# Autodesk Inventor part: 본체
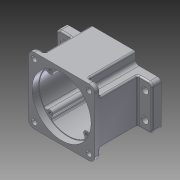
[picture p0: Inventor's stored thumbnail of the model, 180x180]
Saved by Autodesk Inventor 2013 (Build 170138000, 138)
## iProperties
Created: 2015-07
Part Number: 본체
Material: 알루미늄 6061
Document SubType Name: Modeling
Designer: user
Density: 2.71 g/cm^3
Mass: 705.328 g
Surface Area: 672.952 cm^2
Volume: 260.268 cm^3
Author: user
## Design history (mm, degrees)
sketch "스케치1"
  geometry: L1 (-45, 45)-(45, 45); L2 (45, 45)-(45, -45); L3 (45, -45)-(-45, -45); L4 (-45, -45)-(-45, 45); L5 (-45, 45)-(45, -45); L6 (45, 45)-(-45, -45); 1 further point
  constraints: 12 end point, 2 midpoint, 2 parallel, 1 horizontal, 1 perpendicular
  dimensions: "d0" = 90 distance of L2.end L3.end; "d1" = 90 distance of L1.end L2.end
extrude "돌출1" new body sketch "스케치1" distance "d2" = 58; taper "d3" = 0 deg
fillet "모깎기1" dims "d4" = 8
sketch "스케치3"
  geometry: L1 (-37, -45)-(37, -45) reference; L2 (45, -37)-(45, 37) reference; L3 (37, 45)-(-37, 45) reference; L4 (-45, 37)-(-45, -37) reference; L5 (-30, -45)-(30, -45); L6 (30, -45)-(30, 45); L7 (30, 45)-(-30, 45); L8 (-30, 45)-(-30, -45); L9 (-30, -45)-(30, 45); L10 (30, -45)-(-30, 45); L11 (-45, -30)-(45, -30); L12 (45, -30)-(45, 30); L13 (45, 30)-(-45, 30); L14 (-45, 30)-(-45, -30); L15 (-45, -30)-(45, 30); L16 (45, -30)-(-45, 30); A1 r 8 centre (-37, -37) between (-45, -37) and (-37, -45) reference; A2 r 8 centre (37, -37) between (37, -45) and (45, -37) reference; A3 r 8 centre (37, 37) between (45, 37) and (37, 45) reference; A4 r 8 centre (-37, 37) between (-37, 45) and (-45, 37) reference; 1 further point
  constraints: 24 end point, 4 midpoint, 4 parallel, 2 horizontal, 2 perpendicular
  dimensions: "d9" = 60 distance of L7.end L6.end; "d10" = 90 distance of L6.end L5.end; "d11" = 90 distance of L13.end L12.end; "d12" = 60 distance of L12.end L11.end
extrude "돌출2" cut sketch "스케치3" distance "d13" = 51; taper "d14" = 0 deg
sketch "스케치4"
  geometry: L1 (30, -45)-(-30, -45); L2 (-30, -45)-(-30, 45); L3 (-30, 45)-(30, 45); L4 (30, 45)-(30, -45); L5 (30, -45)-(-30, 45); L6 (-30, -45)-(30, 45); L7 (-65, -30)-(65, -30); L8 (65, -30)-(65, 30); L9 (65, 30)-(-65, 30); L10 (-65, 30)-(-65, -30); L11 (-65, -30)-(65, 30); L12 (65, -30)-(-65, 30); 1 further point
  constraints: 24 end point, 4 midpoint, 4 parallel, 2 horizontal, 2 perpendicular
  dimensions: "d15" = 130 distance of L9.end L8.end; "d16" = 60 distance of L8.end L7.end
extrude "돌출3" join sketch "스케치4" distance "d17" = 12; taper "d18" = 0 deg
fillet "모깎기2" dims "d19" = 5
sketch "스케치5"
  geometry: A1 r 8 centre (-37, 37) between (-37, 45) and (-45, 37) reference; A2 r 8 centre (-37, -37) between (-45, -37) and (-37, -45) reference; A3 r 8 centre (37, -37) between (37, -45) and (45, -37) reference; A4 r 8 centre (37, 37) between (45, 37) and (37, 45) reference; 1 further point
hole "구멍1" sketch "스케치5" at (37, 37), (37, -37), (-37, -37), (-37, 37) diameter "d20" = 7; stored, may be unused: countersink angle "d24" = 82 deg, drill point angle "d26" = 118 deg; dims "d21" = 6, "d22" = 3.023, "d23" = 2, "d25" = 8
fillet "모깎기3" dims "d27" = 5
fillet "모깎기5" dims "d29" = 2
sketch "스케치6"
  geometry: L1 (-55, -17.5)-(55, -17.5); L2 (55, -17.5)-(55, 17.5); L3 (55, 17.5)-(-55, 17.5); L4 (-55, 17.5)-(-55, -17.5); L5 (-55, -17.5)-(55, 17.5); L6 (55, -17.5)-(-55, 17.5); 1 further point
  constraints: 12 end point, 2 midpoint, 2 parallel, 1 horizontal, 1 perpendicular
  dimensions: "d30" = 110 distance of L3.end L2.end; "d31" = 35 distance of L2.end L1.end
hole "구멍2" sketch "스케치6" at (-55, -17.5), (-55, 17.5), (55, -17.5), (55, 17.5) diameter "d32" = 9; stored, may be unused: countersink angle "d36" = 82 deg, drill point angle "d38" = 118 deg; dims "d33" = 6, "d34" = 3.023, "d35" = 2, "d37" = 8
sketch "스케치7"
  geometry: C1 r 40 at (0, 0); 1 further point
  constraints: 1 centre point, 1 coincident
  dimensions: "d39" = 80 diameter of C1
extrude "돌출4" cut sketch "스케치7" distance "d40" = 9; taper "d41" = 0 deg
sketch "스케치8"
  geometry: C1 r 40 at (0, 0) reference; C2 r 39 at (0, 0)
  constraints: 1 centre point, 1 coincident
  dimensions: "d42" = 78 diameter of C2
extrude "돌출5" cut sketch "스케치8" distance "d43" = 52; taper "d44" = 0 deg
sketch "스케치9"
  geometry: L1 (0, 0)-(0, 11); L2 (0, 0)-(0, -20); C1 r 39 at (0, 0) reference; A1 r 20.5 centre (0, 11) between (7.402, -8.117) and (-7.402, -8.117); A2 r 14 centre (0, -20) between (-7.402, -8.117) and (7.402, -8.117)
  constraints: 4 end point, 4 point on circle, 2 centre point, 2 coincident, 1 collinear, 1 vertical
  dimensions: "d45" = 11 distance of L1.start L1.end; "d46" = 41 diameter of A1; "d47" = 20 distance of L1.start L2.end; "d48" = 28 diameter of A2
extrude "돌출6" join sketch "스케치9" distance "d49" = 7; taper "d50" = 0 deg
fillet "모깎기6" dims "d51" = 3
sketch "스케치10"
  geometry: C1 r 17.5 at (0, 11); C2 r 11 at (0, -20); A1 r 14 centre (0, -20) between (-10.493, -10.732) and (10.493, -10.732) reference; A2 r 20.5 centre (0, 11) between (11.115, -6.225) and (-11.115, -6.225) reference; 1 further point
  constraints: 2 centre point, 2 coincident
  dimensions: "d52" = 35 diameter of C1; "d53" = 22 diameter of C2
extrude "돌출7" cut sketch "스케치10" distance "d54" = 10; taper "d55" = 0 deg
extrude "돌출8" cut sketch "스케치10" distance "d56" = 7; taper "d57" = 0 deg
sketch "스케치11"
  geometry: C1 r 17.5 at (0, 0) reference; C2 r 12.5 at (0, 0); 1 further point
  constraints: 1 centre point, 1 coincident
  dimensions: "d58" = 25 diameter of C2
extrude "돌출9" cut sketch "스케치11" distance "d59" = 5; taper "d60" = 0 deg
sketch "스케치12"
  geometry: C1 r 11 at (0, 0) reference; C2 r 9.5 at (0, 0); 1 further point
  constraints: 1 centre point, 1 coincident
  dimensions: "d61" = 19 diameter of C2
extrude "돌출10" cut sketch "스케치12" distance "d62" = 1; taper "d63" = 0 deg
fillet "모깎기7" dims "d64" = 2
fillet "모깎기8" dims "d65" = 0.3
fillet "모깎기9" dims "d66" = 0.3
chamfer "모따기1" distance "d67" = 1; stored, may be unused: second distance "d68" = 2, angle "d69" = 45 deg
sketch "스케치13"
  geometry: L1 (30, 35)-(30, 45) reference; L2 (0, 0)-(0, -11); C1 r 25 at (0, -11); 1 further point
  constraints: 2 end point, 1 centre point, 1 coincident, 1 parallel
  dimensions: "d71" = 11 distance of L2.start L2.end; "d72" = 50 diameter of C1
extrude "돌출11" join sketch "스케치13" distance "d73" = 7; taper "d74" = 0 deg
sketch "스케치14"
  geometry: C1 r 25 at (0, 0) reference; C2 r 16 at (0, 0); 1 further point
  constraints: 1 centre point, 1 coincident
  dimensions: "d75" = 32 diameter of C2
extrude "돌출12" cut sketch "스케치14" distance "d76" = 8; taper "d77" = 0 deg
chamfer "모따기2" distance "d78" = 1; stored, may be unused: second distance "d79" = 2, angle "d80" = 45 deg
fillet "모깎기10" dims "d81" = 2
fillet "모깎기11" dims "d82" = 0.3
sketch "스케치15"
  geometry: L1 (0, 0)-(43.477, 43.477); L2 (0, 0)-(61.486, 0); C1 r 40 at (0, 0) reference; C2 r 4 at (24.749, 24.749); A1 r 39 centre (0, 0) between (21.134, 32.777) and (32.777, 21.134) reference; A2 r 35 centre (0, 0) between (24.749, 24.749) and (21.762, 27.412); A3 r 3.5 centre (29.836, 19.238) between (32.777, 21.134) and (27.412, 21.762); A4 r 3.5 centre (19.238, 29.836) between (21.762, 27.412) and (21.134, 32.777)
  constraints: 9 point on circle, 4 centre point, 4 end point, 2 tangent, 1 coincident, 1 equal length, 1 horizontal, 1 point on line, 1 symmetric about line, 1 other
  dimensions: "d83" = 70 diameter of A2; "d84" = 45 deg angle of L2 L1; "d85" = 8 diameter of C2; "d86" = 7 diameter of A3
extrude "돌출13" join sketch "스케치15" stored distance "d87" = 8; taper "d88" = 0 deg
fillet "모깎기12" dims "d92" = 2
sketch "스케치16"
  geometry: A1 r 4 centre (24.749, 24.749) between (21.763, 27.411) and (27.411, 21.763) reference; A2 r 4 centre (24.749, -24.749) between (27.411, -21.763) and (21.763, -27.411) reference; A3 r 4 centre (-24.749, -24.749) between (-21.763, -27.411) and (-27.411, -21.763) reference; A4 r 4 centre (-24.749, 24.749) between (-27.411, 21.763) and (-21.763, 27.411) reference
hole "구멍3" sketch "스케치16" at (-24.749, 24.749), (24.749, 24.749), (24.749, -24.749), (-24.749, -24.749) diameter "d93" = 3.459; stored, may be unused: countersink angle "d97" = 82 deg, drill point angle "d99" = 118 deg; dims "d94" = 12, "d95" = 3.023, "d96" = 2, "d98" = 15
sketch "스케치17"
  geometry: L1 (30, 45)-(-30, 45) reference; L2 (30, 35)-(30, 45) reference; L3 (0, 45)-(0, 30); 5 further points
  constraints: 2 end point, 1 coincident, 1 midpoint, 1 parallel, 1 other
  dimensions: "d101" = 15 distance of L3.start L3.end
feature "엠보싱1" sketch "스케치17" dims "d102" = 0.5, "d103" = 0
fillet "모깎기26" dims "d116" = 2
fillet "모깎기27" dims "d117" = 2
fillet "모깎기28" dims "d118" = 2
fillet "모깎기29" dims "d119" = 2
node "솔리드1"
pattern_circular "원형 패턴1" dims angle "d90" = 360 deg
